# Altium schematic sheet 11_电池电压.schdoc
size 309 x 223 mm; Symbol: Sheet-Symbol_A4; Device: Sheet-Symbol_A4; Company: 嘉立创EDA; Version: V1.0; Page Size: A4; @Project Name: 共享电动车中控; @Page Count: 11; @Update Date: 2024-11-20; @Create Date: 2024-10-05; @Schematic Name: SCH; @Page No: 11; @Page Name: 电池电压; @Board Name: STM32F103C8T6; @Create Time: 22:37:28; @Update Time: 15:37:20
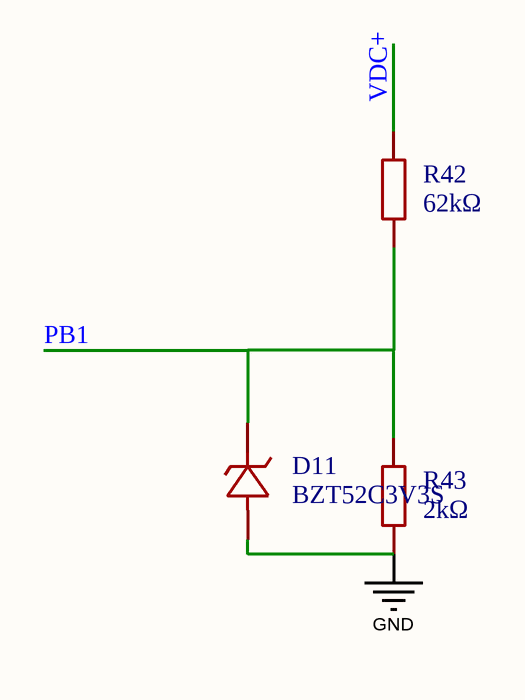
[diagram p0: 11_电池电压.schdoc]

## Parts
D11  BZT52C3V3S  [SOD-323_L1.7-W1.3-LS2.6-RD]  (value not drawn)
R42  62kΩ  [R0603]  (value not drawn)
R43  2kΩ  [R0805]  (value not drawn)

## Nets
GND: D11.2(A) R43.1
PB1: D11.1(K) R42.2 R43.2
VDC+: R42.1

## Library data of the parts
D11 = BZT52C3V3S_C19077437: 二极管配置:独立式;稳压值(标称值):3.3V;稳压值(范围):3.1V~3.5V;功率(Pd):200mW;; Manufacturer: 宏迦橙; Add into BOM: yes; Diode Configuration: 独立式; Zener Voltage (Nom): 3.3V; Reverse Leakage Current (Ir): 5uA@1V; Power Dissipation: 200mW; Zener Impedance (Zzt): 95Ω
R42 = 0603WAF6202T5E: 电阻类型:厚膜电阻;阻值:62kΩ;精度:±1%;功率:100mW;最大工作电压:75V;温度系数:±100ppm/℃;; Manufacturer: UNI-ROYAL(厚声); Add into BOM: yes; Tolerance: ±1%; Power(Watts): 100mW; Overload Voltage (Max): 75V
R43 = 0805W8F2001T5E: 电阻类型:厚膜电阻;阻值:2kΩ;精度:±1%;功率:125mW;最大工作电压:150V;温度系数:±100ppm/℃;; Manufacturer: UNI-ROYAL(厚声); Symbol: 0603WAF2001T5E; Add into BOM: yes; Tolerance: ±1%; Power(Watts): 125mW; Overload Voltage (Max): 150V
